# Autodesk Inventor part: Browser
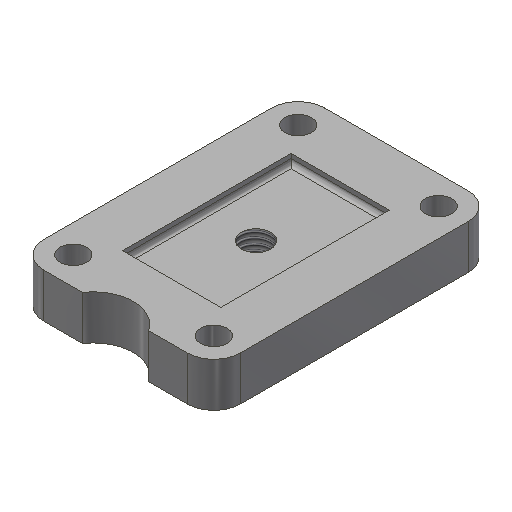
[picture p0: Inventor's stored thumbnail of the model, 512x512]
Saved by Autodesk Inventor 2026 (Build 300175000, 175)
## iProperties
Shininess: 64.0
Length Units: 11269
Angle Units: 11279
Time Units: 11290
Mass Units: 11286
Length Display Precision: 3
Angle Display Precision: 2
Compacted: True
Part Number: Browser
Document SubType Name: Modeling
Created: 2003-11
Designer: Autodesk, Inc.
Manufacturer: Standard
Standards Organization: Custom
Mass: 239.386 g
Surface Area: 93.2455 cm^2
Volume: 30.4562 cm^3
Density: 7.86 g/cm^3
Material: Steel, Mild
Appearance: Steel
Density: 0.0
Volumn: 0.0
Area: 0.0
PropertySet Name: Model Information
Control State: 0
Master: False
Checked Out: False
Author: Autodesk, Inc.
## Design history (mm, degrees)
sketch "Sketch1"
  geometry: L1 (0, 0)-(44.45, 0); L2 (44.45, 0)-(44.45, 63.5); L3 (44.45, 63.5)-(0, 63.5); L4 (0, 63.5)-(0, 0)
  constraints: 8 end point, 2 parallel, 1 horizontal, 1 perpendicular
  dimensions: "d0" = 44.45 distance between parallel lines of L2 L4; "d1" = 63.5 distance of L1.end L2.end
extrude "Extrusion1" new body sketch "Sketch1" distance "d2" = 10; taper "d3" = 0 deg
sketch "Sketch2"
  geometry: L1 (0, 0)-(0, 63.5) reference; L2 (44.45, 0)-(0, 0) reference; L3 (44.45, 63.5)-(44.45, 0) reference; L4 (0, 63.5)-(44.45, 63.5) reference; L5 (0, 31.75)-(44.45, 31.75); 4 further points
  constraints: 2 end point, 2 midpoint, 2 symmetric about line
  dimensions: "d4" = 6.35 distance from line of point (6.35, 57.15) L4; "d5" = 6.35 distance from line of L4 point (38.1, 57.15); "d6" = 6.35 distance from line of L1 point (6.35, 57.15); "d7" = 6.35 distance from line of L3 point (38.1, 57.15)
hole "Hole1" sketch "Sketch2" diameter "d8" = 6; stored, may be unused: countersink angle "d12" = 82 deg, drill point angle "d14" = 118 deg; dims "d9" = 12.7, "d10" = 9.525, "d11" = 6.35, "d13" = 10
sketch "Sketch3"
  geometry: L1 (11.125, 50.8)-(33.35, 50.8); L2 (33.35, 50.8)-(33.35, 12.7); L3 (33.35, 12.7)-(11.125, 12.7); L4 (11.125, 12.7)-(11.125, 50.8); L5 (44.45, 57.5)-(44.45, 6) reference; L6 (38.45, 0)-(6, 0) reference
  constraints: 8 end point, 2 parallel, 1 horizontal, 1 perpendicular
  dimensions: "d16" = 11.0998 distance between parallel lines of L5 L2; "d17" = 22.225 distance between parallel lines of L2 L4; "d18" = 12.7 distance between parallel lines of L6 L3; "d19" = 38.1 distance between parallel lines of L3 L1
extrude "Extrusion2" cut sketch "Sketch3" distance "d20" = 2; taper "d21" = 0 deg
sketch "Sketch4"
  geometry: L1 (44.45, 63.5)-(44.45, 0) reference; L2 (44.45, 0)-(0, 0) reference; C1 r 3 at (6.35, 57.15) reference; 3 further points
  constraints: 2 midpoint, 1 horizontal alignment, 1 vertical alignment
hole "Hole2" sketch "Sketch4" diameter "d25" = 6.647; stored, may be unused: countersink angle "d29" = 82 deg, drill point angle "d31" = 118 deg; dims "d26" = 5, "d27" = 9.525, "d28" = 6.35, "d30" = 19.05
sketch "Sketch5"
  geometry: L1 (-44.45, 63.5)-(0, 63.5) reference; C1 r 9 at (-22.225, 68.5); 1 further point
  constraints: 1 centre point, 1 midpoint, 1 vertical alignment
  dimensions: "d41" = 5 distance from line of L1 C1.centre; "d42" = 18 diameter of C1
extrude "Extrusion3" cut sketch "Sketch5" extent not by distance; stored distance "d33" = 25.4; taper "d34" = 0 deg
fillet "Fillet3" dims "d39" = 1
fillet "Fillet4" dims "d40" = 6
body "Solid1"
node "Projected Loop1"
